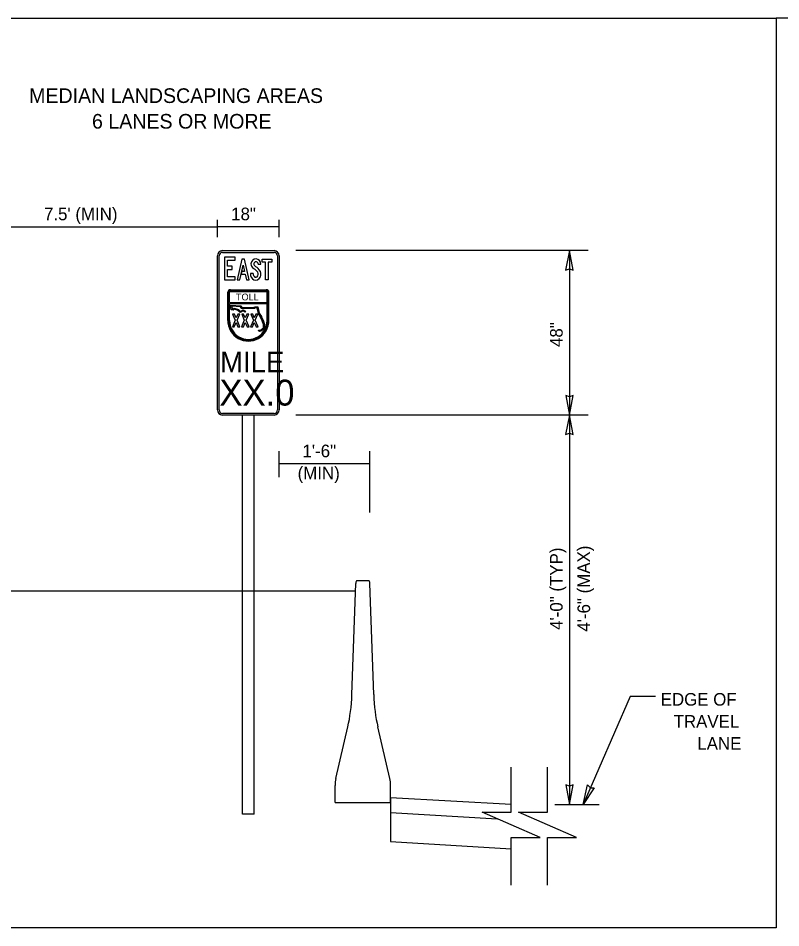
# Model space of a CAD drawing. Extents: x 57428 to 58066, y 11696 to 12105.
# Drawn here: x 57541.3 to 57710.6, y 11732.3 to 11934.3 of the extents above; entities that cross this region are included whole.
import ezdxf

# ---------------------------------------------------------------- set-up
doc = ezdxf.new("R2010")
doc.units = 0
for name, color, linetype in [('Default', 7, 'Continuous'), ('DimLines_dp', 7, 'Continuous'), ('NonPlottingEle_dp', 7, 'Continuous'), ('SignPanel', 7, 'Continuous'), ('TextMisc', 7, 'Continuous'), ('TextTables', 7, 'Continuous'), ('XSGrdLine_ex', 7, 'Continuous')]:
    doc.layers.add(name, color=color, linetype=linetype)

msp = doc.modelspace()

# ---------------------------------------------------------------- linework, layer by layer
at = {"layer": 'Default'}
for points in [[(57650.73, 11741.8), (57650.73, 11752.36), (57657.19, 11752.36), (57650.73, 11755.17), (57644.27, 11757.99), (57650.73, 11757.99), (57650.73, 11767.99)], [(57658.79, 11741.8), (57658.79, 11752.36), (57665.26, 11752.36), (57658.79, 11755.17), (57652.33, 11757.99), (57658.79, 11757.99), (57658.79, 11767.99)]]:
    msp.add_lwpolyline(points, dxfattribs=at)
at = {"layer": 'DimLines_dp'}
for p, q in [((57585.54, 11885.65), (57585.54, 11889.48)), ((57599.23, 11885.65), (57599.23, 11889.48)), ((57524.88, 11887.93), (57585.54, 11887.93)), ((57599.23, 11887.93), (57585.54, 11887.93)), ((57667.81, 11882.65), (57602.97, 11882.65)), ((57663.67, 11882.65), (57662.83, 11878.3)), ((57663.67, 11882.65), (57663.67, 11846.15)), ((57664.48, 11878.3), (57663.67, 11882.65)), ((57662.83, 11878.3), (57663.67, 11878.63)), ((57663.67, 11878.63), (57664.48, 11878.3)), ((57663.67, 11852.14), (57663.67, 11759.71)), ((57663.67, 11850.17), (57662.86, 11850.5)), ((57662.86, 11850.5), (57663.67, 11846.15)), ((57663.67, 11850.17), (57662.86, 11850.5)), ((57662.86, 11850.5), (57663.67, 11846.15)), ((57663.67, 11846.15), (57664.51, 11850.5)), ((57664.51, 11850.5), (57663.67, 11850.17)), ((57663.67, 11846.15), (57664.51, 11850.5)), ((57664.51, 11850.5), (57663.67, 11850.17)), ((57667.81, 11846.15), (57602.97, 11846.15)), ((57663.67, 11846.15), (57662.83, 11841.8)), ((57664.48, 11841.8), (57663.67, 11846.15)), ((57662.83, 11841.8), (57663.67, 11842.13)), ((57663.67, 11842.13), (57664.48, 11841.8)), ((57599.23, 11832.39), (57599.23, 11838.14)), ((57619.37, 11824.54), (57619.37, 11838.14)), ((57619.37, 11835.3), (57599.23, 11835.3)), ((57677.15, 11783.68), (57666.72, 11759.71)), ((57682.8, 11783.68), (57677.15, 11783.68)), ((57663.67, 11763.73), (57662.86, 11764.06)), ((57662.86, 11764.06), (57663.67, 11759.71)), ((57663.67, 11759.71), (57664.51, 11764.06)), ((57664.51, 11764.06), (57663.67, 11763.73)), ((57666.72, 11759.71), (57667.69, 11764.03)), ((57669.2, 11763.37), (57666.72, 11759.71)), ((57667.69, 11764.03), (57668.33, 11763.39)), ((57668.33, 11763.39), (57669.2, 11763.37)), ((57660.46, 11759.71), (57670.24, 11759.71))]:
    msp.add_line(p, q, dxfattribs=at)
at = {"layer": 'NonPlottingEle_dp'}
for p, q in [((57591.06, 11807.11), (57591.06, 11846.15)), ((57593.72, 11807.11), (57593.72, 11846.15)), ((57591.06, 11757.53), (57591.06, 11807.11)), ((57593.72, 11757.53), (57593.72, 11807.11)), ((57593.72, 11757.53), (57591.06, 11757.53))]:
    msp.add_line(p, q, dxfattribs=at)
at = {"layer": 'SignPanel'}
for p, q in [((57594.58, 11879.64), (57595.16, 11879.64)), ((57594.58, 11879.64), (57595.16, 11879.64)), ((57594.58, 11879.64), (57595.16, 11879.64)), ((57593.44, 11877.6), (57592.85, 11877.6)), ((57593.44, 11877.6), (57592.85, 11877.6)), ((57593.44, 11877.6), (57592.85, 11877.6)), ((57588.4, 11873.98), (57596.38, 11873.98)), ((57587.83, 11867.13), (57587.83, 11873.41)), ((57588.02, 11867.13), (57588.02, 11873.41)), ((57588.2, 11871.13), (57588.2, 11873.41)), ((57588.4, 11873.79), (57596.38, 11873.79)), ((57588.4, 11873.6), (57596.38, 11873.6)), ((57596.57, 11871.13), (57596.57, 11873.41)), ((57596.76, 11867.13), (57596.76, 11873.41)), ((57596.95, 11867.13), (57596.95, 11873.41)), ((57588.2, 11871.13), (57596.57, 11871.13)), ((57588.2, 11867.13), (57588.2, 11870.94)), ((57588.2, 11870.94), (57596.57, 11870.94)), ((57588.59, 11869.48), (57588.42, 11870.57)), ((57588.42, 11870.57), (57590.8, 11870.39)), ((57590.64, 11870.17), (57588.69, 11870.32)), ((57588.69, 11870.32), (57588.79, 11869.69)), ((57589.68, 11870.23), (57589.68, 11870.23)), ((57590.78, 11869.81), (57590.64, 11870.17)), ((57590.8, 11870.39), (57590.93, 11870.04)), ((57590.93, 11870.04), (57593.66, 11870.04)), ((57593.66, 11870.04), (57593.77, 11870.19)), ((57593.77, 11870.19), (57594.5, 11870.19)), ((57593.89, 11869.97), (57593.79, 11869.81)), ((57594.32, 11869.97), (57593.89, 11869.97)), ((57594.62, 11868.67), (57594.32, 11869.97)), ((57594.5, 11870.19), (57594.83, 11868.76)), ((57596.57, 11867.13), (57596.57, 11870.94)), ((57589.04, 11869.42), (57588.59, 11869.48)), ((57588.79, 11869.69), (57588.98, 11869.66)), ((57588.98, 11869.66), (57589.25, 11869.88)), ((57589.29, 11869.62), (57589.04, 11869.42)), ((57589.25, 11869.88), (57590.17, 11869.58)), ((57590.05, 11869.37), (57589.29, 11869.62)), ((57590.59, 11868.88), (57590.05, 11869.37)), ((57590.17, 11869.58), (57590.62, 11869.16)), ((57591.22, 11869.25), (57590.59, 11868.88)), ((57590.62, 11869.16), (57591.23, 11869.52)), ((57593.79, 11869.81), (57590.78, 11869.81)), ((57591.6, 11868.99), (57591.22, 11869.25)), ((57591.23, 11869.52), (57591.73, 11869.18)), ((57591.73, 11869.18), (57591.6, 11868.99)), ((57595.06, 11867.97), (57594.62, 11868.67)), ((57594.83, 11868.76), (57595.29, 11868.04)), ((57595.06, 11867.79), (57595.06, 11867.97)), ((57595.29, 11868.04), (57595.29, 11867.85)), ((57595.48, 11867.09), (57595.06, 11867.79)), ((57595.29, 11867.85), (57595.7, 11867.18)), ((57595.72, 11866.23), (57595.48, 11867.09)), ((57595.7, 11867.18), (57595.95, 11866.26)), ((57595.72, 11865.5), (57595.72, 11866.23)), ((57595.95, 11866.26), (57595.95, 11865.39)), ((57594.61, 11864.85), (57594.74, 11865.04)), ((57594.84, 11864.69), (57594.61, 11864.85)), ((57594.74, 11865.04), (57594.89, 11864.94)), ((57595.2, 11864.78), (57594.84, 11864.69)), ((57594.89, 11864.94), (57595.09, 11864.99)), ((57595.09, 11864.99), (57595.72, 11865.5)), ((57595.95, 11865.39), (57595.2, 11864.78))]:
    msp.add_line(p, q, dxfattribs=at)
for points in [[(57586.68, 11882.65), (57598.09, 11882.65)], [(57586.68, 11882.27), (57598.09, 11882.27)], [(57585.54, 11847.29), (57585.54, 11881.51)], [(57585.92, 11847.29), (57585.92, 11881.51)], [(57598.85, 11881.51), (57598.85, 11847.29)], [(57599.23, 11881.51), (57599.23, 11847.29)], [(57598.09, 11846.53), (57586.68, 11846.53)], [(57598.09, 11846.15), (57586.68, 11846.15)]]:
    msp.add_lwpolyline(points, dxfattribs=at)
for points in [[(57587.75, 11876.87), (57587.75, 11878.49), (57588.77, 11878.49), (57588.77, 11879.2), (57587.75, 11879.2), (57587.75, 11880.52), (57589.47, 11880.52), (57589.47, 11881.23), (57587.09, 11881.23), (57587.09, 11876.16), (57589.47, 11876.16), (57589.47, 11876.87)], [(57587.75, 11876.87), (57587.75, 11878.49), (57588.77, 11878.49), (57588.77, 11879.2), (57587.75, 11879.2), (57587.75, 11880.52), (57589.47, 11880.52), (57589.47, 11881.23), (57587.09, 11881.23), (57587.09, 11876.16), (57589.47, 11876.16), (57589.47, 11876.87)], [(57587.75, 11876.87), (57587.75, 11878.49), (57588.77, 11878.49), (57588.77, 11879.2), (57587.75, 11879.2), (57587.75, 11880.52), (57589.47, 11880.52), (57589.47, 11881.23), (57587.09, 11881.23), (57587.09, 11876.16), (57589.47, 11876.16), (57589.47, 11876.87)], [(57591.72, 11877.39), (57591.99, 11876.16), (57592.59, 11876.16), (57591.57, 11880.74), (57590.94, 11880.74), (57589.92, 11876.16), (57590.53, 11876.16), (57590.8, 11877.39)], [(57590.95, 11878.03), (57590.8, 11877.39), (57591.72, 11877.39), (57591.99, 11876.16), (57592.59, 11876.16), (57591.57, 11880.74), (57590.94, 11880.74), (57589.92, 11876.16), (57590.53, 11876.16), (57591.26, 11879.44), (57591.57, 11878.03)], [(57590.95, 11878.03), (57590.8, 11877.39), (57591.72, 11877.39), (57591.99, 11876.16), (57592.59, 11876.16), (57591.57, 11880.74), (57590.94, 11880.74), (57589.92, 11876.16), (57590.53, 11876.16), (57591.26, 11879.44), (57591.57, 11878.03)], [(57596.23, 11880.1), (57595.45, 11880.1), (57595.45, 11880.74), (57597.59, 11880.74), (57597.59, 11880.1), (57596.81, 11880.1), (57596.81, 11876.16), (57596.23, 11876.16)], [(57596.23, 11880.1), (57595.45, 11880.1), (57595.45, 11880.74), (57597.59, 11880.74), (57597.59, 11880.1), (57596.81, 11880.1), (57596.81, 11876.16), (57596.23, 11876.16)], [(57596.23, 11880.1), (57595.45, 11880.1), (57595.45, 11880.74), (57597.59, 11880.74), (57597.59, 11880.1), (57596.81, 11880.1), (57596.81, 11876.16), (57596.23, 11876.16)], [(57591.26, 11879.44), (57591.57, 11878.03), (57590.95, 11878.03)], [(57589.28, 11865.71), (57589.69, 11866.69), (57590.09, 11865.71), (57590.52, 11865.71), (57589.9, 11867.2), (57590.47, 11868.57), (57590.04, 11868.57), (57589.69, 11867.71), (57589.33, 11868.57), (57588.9, 11868.57), (57589.47, 11867.2), (57588.85, 11865.71)], [(57591.29, 11865.71), (57591.7, 11866.69), (57592.11, 11865.71), (57592.54, 11865.71), (57591.91, 11867.2), (57592.49, 11868.57), (57592.06, 11868.57), (57591.7, 11867.71), (57591.34, 11868.57), (57590.92, 11868.57), (57591.49, 11867.2), (57590.87, 11865.71)], [(57593.31, 11865.71), (57593.72, 11866.69), (57594.13, 11865.71), (57594.55, 11865.71), (57593.93, 11867.2), (57594.5, 11868.57), (57594.08, 11868.57), (57593.72, 11867.71), (57593.36, 11868.57), (57592.93, 11868.57), (57593.5, 11867.2), (57592.88, 11865.71)]]:
    msp.add_lwpolyline(points, close=True, dxfattribs=at)
for centre, radius, start, end in [((57586.68, 11881.51), 1.14, 90, 180), ((57586.68, 11881.51), 0.76, 90, 180), ((57598.09, 11881.51), 1.14, 0, 90), ((57598.09, 11881.51), 0.76, 0, 90), ((57586.68, 11847.29), 1.14, 180, 270), ((57586.68, 11847.29), 0.76, 180, 270), ((57598.09, 11847.29), 1.14, 270, 360), ((57598.09, 11847.29), 0.76, 270, 360)]:
    msp.add_arc(centre, radius, start, end, dxfattribs=at)
for centre, major_axis, ratio, start_param, end_param in [((57594.07, 11879.61), (0, 1.19), 0.91923, 4.736267, 7.790596), ((57594.07, 11879.61), (0, 1.19), 0.91923, 4.736267, 7.790596), ((57594.07, 11879.61), (0, 1.19), 0.91923, 4.736267, 7.790596), ((57594.07, 11879.6), (0, 0.558), 0.91923, 4.786904, 7.140738), ((57594.07, 11879.6), (0, 0.558), 0.91923, 4.786904, 7.140738), ((57594.07, 11879.6), (0, 0.558), 0.91923, 4.786904, 7.140738), ((57593.96, 11879.65), (0, 1.07), 0.91923, 1.534831, 2.511766), ((57593.96, 11879.65), (0, 1.07), 0.91923, 1.534831, 2.511766), ((57593.96, 11879.65), (0, 1.07), 0.91923, 1.534831, 2.511766), ((57591.36, 11874.71), (0, 4.63), 0.91923, 5.515137, 5.786988), ((57591.36, 11874.71), (0, 4.63), 0.91923, 5.515137, 5.786988), ((57591.36, 11874.71), (0, 4.63), 0.91923, 5.515137, 5.786988), ((57594, 11879.67), (0, 0.46), 0.91923, 0.87378, 2.656959), ((57594, 11879.67), (0, 0.46), 0.91923, 0.87378, 2.656959), ((57594, 11879.67), (0, 0.46), 0.91923, 0.87378, 2.656959), ((57591.87, 11875.41), (0, 4.39), 0.91923, 5.462886, 5.782242), ((57591.87, 11875.41), (0, 4.39), 0.91923, 5.462886, 5.782242), ((57591.87, 11875.41), (0, 4.39), 0.91923, 5.462886, 5.782242), ((57593.88, 11877.41), (0, 0.792), 0.91923, 4.254409, 5.632398), ((57593.88, 11877.41), (0, 0.792), 0.91923, 4.254409, 5.632398), ((57593.88, 11877.41), (0, 0.792), 0.91923, 4.254409, 5.632398), ((57593.89, 11877.41), (0, 1.42), 0.91923, 4.260987, 5.485755), ((57593.89, 11877.41), (0, 1.42), 0.91923, 4.260987, 5.485755), ((57593.89, 11877.41), (0, 1.42), 0.91923, 4.260987, 5.485755), ((57594.22, 11877.53), (0, 1.5), 0.91923, 1.526364, 2.701682), ((57594.22, 11877.53), (0, 1.5), 0.91923, 1.526364, 2.701682), ((57594.22, 11877.53), (0, 1.5), 0.91923, 1.526364, 2.701682), ((57594.28, 11877.56), (0, 0.911), 0.91923, 1.524757, 2.28214), ((57594.28, 11877.56), (0, 0.911), 0.91923, 1.524757, 2.28214), ((57594.28, 11877.56), (0, 0.911), 0.91923, 1.524757, 2.28214), ((57594.04, 11877.35), (0, 1.24), 0.91923, 2.786047, 4.251692), ((57594.04, 11877.35), (0, 1.24), 0.91923, 2.786047, 4.251692), ((57594.04, 11877.35), (0, 1.24), 0.91923, 2.786047, 4.251692), ((57594.06, 11877.33), (0, 0.581), 0.91923, 2.261787, 4.23006), ((57594.06, 11877.33), (0, 0.581), 0.91923, 2.261787, 4.23006), ((57594.06, 11877.33), (0, 0.581), 0.91923, 2.261787, 4.23006), ((57588.4, 11873.41), (0, 0.57), 0.9997, 0, 1.570796), ((57596.38, 11873.41), (0, 0.57), 0.9997, 4.712389, 6.283185), ((57588.4, 11873.41), (0, 0.38), 0.9997, 0, 1.570796), ((57588.4, 11873.41), (0, 0.19), 0.9997, 0, 1.570796), ((57596.38, 11873.41), (0, 0.38), 0.9997, 4.712389, 6.283185), ((57596.38, 11873.41), (0, 0.19), 0.9997, 4.712389, 6.283185), ((57592.39, 11867.13), (0, -4.56), 0.9997, 4.712389, 7.853982), ((57592.39, 11867.13), (0, -4.37), 0.9997, 4.712389, 7.853982), ((57592.39, 11867.13), (0, -4.18), 0.9997, 4.712389, 7.853982)]:
    msp.add_ellipse(centre, major_axis=major_axis, ratio=ratio, start_param=start_param, end_param=end_param, dxfattribs=at)
at = {"layer": 'TextMisc'}
msp.add_line((58065.89, 11934.25), (57709.55, 11934.25), dxfattribs=at)
msp.add_lwpolyline([(57449.89, 11934.25), (57709.55, 11934.25), (57709.55, 11732.32), (57449.89, 11732.32)], close=True, dxfattribs=at)
at = {"layer": 'XSGrdLine_ex'}
for p, q in [((57616.5, 11809.43), (57619.11, 11809.43)), ((57615.38, 11784.12), (57616.24, 11808.74)), ((57620.23, 11784.12), (57619.37, 11808.74)), ((57494.48, 11807.11), (57616.18, 11807.11)), ((57611.81, 11765.45), (57614.48, 11776.9)), ((57623.8, 11765.45), (57621.13, 11776.9)), ((57611.64, 11760.13), (57611.64, 11763.91)), ((57623.97, 11760.13), (57623.97, 11763.91)), ((57623.97, 11761.2), (57623.97, 11760.13)), ((57650.73, 11759.71), (57623.97, 11761.2)), ((57611.64, 11760.13), (57623.97, 11760.13)), ((57623.97, 11760.13), (57623.97, 11751.48)), ((57623.97, 11757.95), (57647.62, 11756.53)), ((57623.97, 11751.48), (57650.73, 11749.87))]:
    msp.add_line(p, q, dxfattribs=at)
for centre, major_axis, start_param, end_param in [((57616.5, 11808.66), (0, 0.77), 0, 1.465919), ((57619.11, 11808.66), (0, 0.77), 4.817266, 6.283185), ((57610.27, 11785.73), (0, -15.4), 0.96007, 1.465919), ((57625.34, 11785.73), (0, -15.4), 4.817266, 5.323115), ((57612.54, 11763.91), (0, 2.7), 0.96007, 1.570796), ((57623.07, 11763.91), (0, 2.7), 4.712389, 5.323115)]:
    msp.add_ellipse(centre, major_axis=major_axis, ratio=0.333333, start_param=start_param, end_param=end_param, dxfattribs=at)

# ---------------------------------------------------------------- texts
at = {"layer": 'DimLines_dp'}
for s, p in [("7.5' (MIN)", (57547.03, 11889.4)), ('18"', (57588.58, 11889.4)), ('1\'-6"', (57604.41, 11836.78)), ('(MIN)', (57603.33, 11831.88)), ('EDGE OF ', (57683.94, 11781.64)), ('TRAVEL ', (57686.81, 11776.74)), ('LANE', (57692.07, 11771.84))]:
    msp.add_text(s, height=2.8, dxfattribs=at).set_placement(p)
for s, p in [('48"', (57662.17, 11861.26)), ('4\'-0" (TYP)', (57662.17, 11798.46)), ('4\'-6" (MAX)', (57668.26, 11798.06))]:
    msp.add_text(s, height=2.8, rotation=90, dxfattribs=at).set_placement(p)
at = {"layer": 'SignPanel'}
for s, height, p in [('TOLL', 1.519, (57589.63, 11871.6)), ('MILE', 4.562, (57586.13, 11855.65)), ('XX.0', 5.75, (57585.97, 11848.25))]:
    msp.add_text(s, height=height, rotation=360, dxfattribs=at).set_placement(p)
at = {"layer": 'TextTables'}
for s, p in [('MEDIAN LANDSCAPING AREAS', (57543.72, 11915.43)), ('6 LANES OR MORE', (57557.68, 11909.74))]:
    msp.add_text(s, height=3.2524, dxfattribs=at).set_placement(p)

doc.saveas('drawing.dxf')
